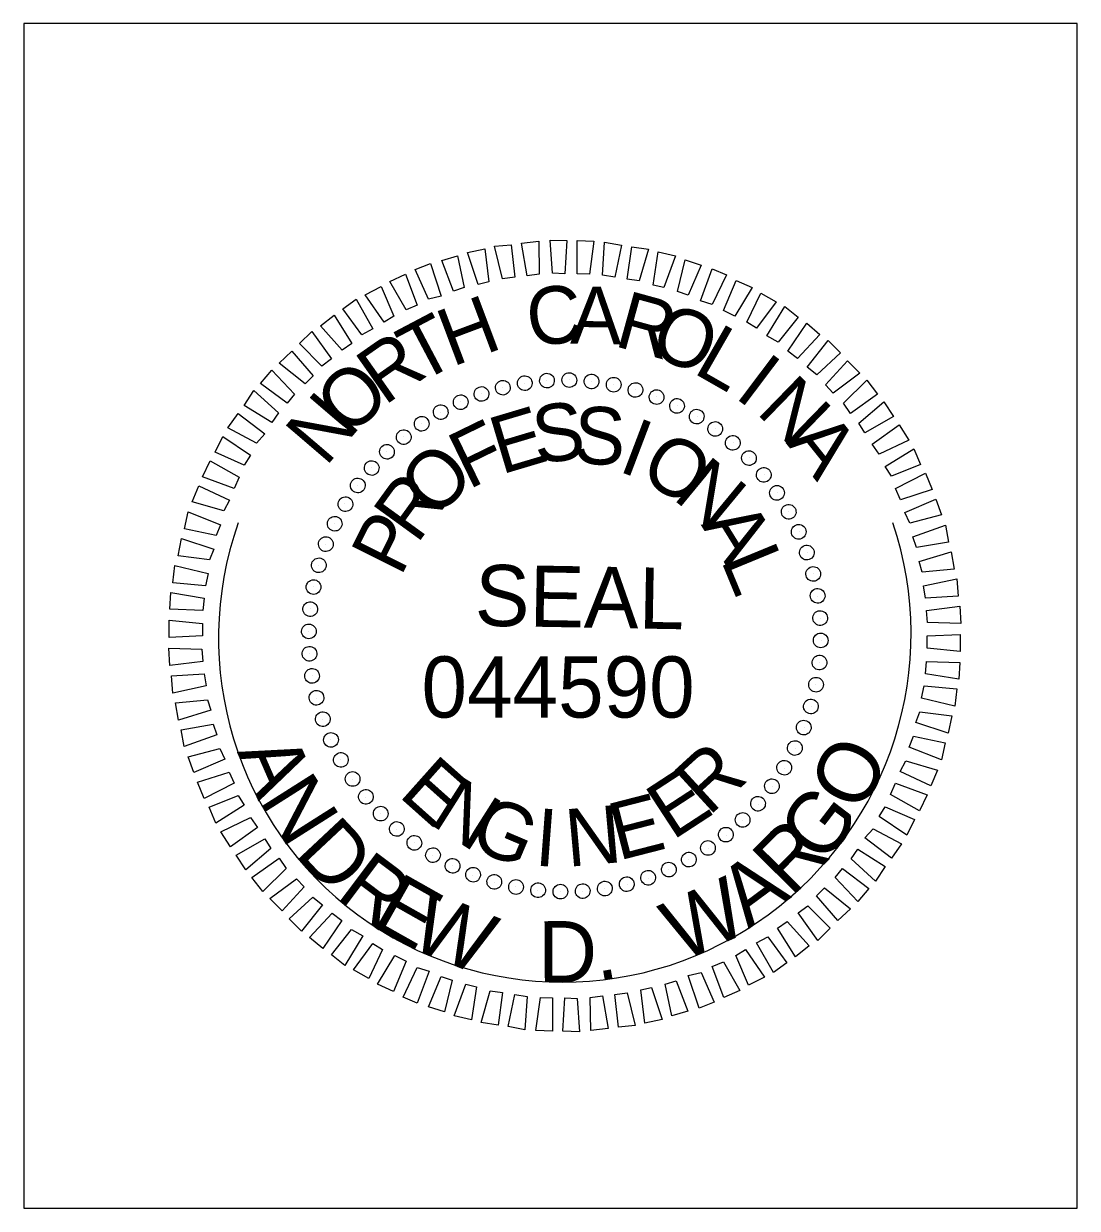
# Model space of a CAD drawing. Extents: x 1882804 to 1884487, y 844572 to 845443.
# Drawn here: x 1884386.6 to 1884486.6, y 845330.9 to 845443.4 of the extents above; entities that cross this region are included whole.
import ezdxf

# ---------------------------------------------------------------- set-up
doc = ezdxf.new("R2010")
doc.units = 0
for name, color, linetype in [('Scratch_Level_1', 7, 'Continuous'), ('Sheet PE Seal Cell', 7, 'Continuous'), ('Sheet Plot Border Inside CELL', 7, 'Continuous')]:
    doc.layers.add(name, color=color, linetype=linetype)

msp = doc.modelspace()

# ---------------------------------------------------------------- linework, layer by layer
at = {"layer": 'Scratch_Level_1'}
msp.add_lwpolyline([(1884386.6, 845330.93), (1884486.6, 845330.93), (1884486.6, 845443.43), (1884386.6, 845443.43)], close=True, dxfattribs=at)
at = {"layer": 'Sheet PE Seal Cell'}
for p, q in [((1884436.27, 845409.56), (1884436.27, 845409.56)), ((1884438.4, 845409.6), (1884438.4, 845409.6)), ((1884440.53, 845409.46), (1884440.53, 845409.46)), ((1884430.02, 845408.3), (1884430.02, 845408.3)), ((1884432.05, 845408.88), (1884432.05, 845408.88)), ((1884434.18, 845409.26), (1884434.18, 845409.26)), ((1884442.61, 845409.12), (1884442.61, 845409.12)), ((1884444.65, 845408.68), (1884444.65, 845408.68)), ((1884428.08, 845407.52), (1884428.08, 845407.52)), ((1884446.68, 845408.01), (1884446.68, 845408.01)), ((1884448.62, 845407.13), (1884448.62, 845407.13)), ((1884426.19, 845406.55), (1884426.19, 845406.55)), ((1884450.51, 845406.16), (1884450.51, 845406.16)), ((1884424.35, 845405.44), (1884424.35, 845405.44)), ((1884452.25, 845404.95), (1884452.25, 845404.95)), ((1884422.66, 845404.23), (1884422.66, 845404.23)), ((1884421.06, 845402.77), (1884421.06, 845402.77)), ((1884453.95, 845403.65), (1884453.95, 845403.65)), ((1884455.45, 845402.19), (1884455.45, 845402.19)), ((1884419.6, 845401.27), (1884419.6, 845401.27)), ((1884456.9, 845400.59), (1884456.9, 845400.59)), ((1884418.3, 845399.58), (1884418.3, 845399.58)), ((1884458.11, 845398.9), (1884458.11, 845398.9)), ((1884417.09, 845397.83), (1884417.09, 845397.83)), ((1884459.23, 845397.06), (1884459.23, 845397.06)), ((1884416.12, 845395.94), (1884416.12, 845395.94)), ((1884460.2, 845395.17), (1884460.2, 845395.17)), ((1884415.25, 845394.01), (1884415.25, 845394.01)), ((1884460.97, 845393.23), (1884460.97, 845393.23)), ((1884414.57, 845391.97), (1884414.57, 845391.97)), ((1884461.55, 845391.2), (1884461.55, 845391.2)), ((1884414.13, 845389.94), (1884414.13, 845389.94)), ((1884461.94, 845389.07), (1884461.94, 845389.07)), ((1884413.79, 845387.86), (1884413.79, 845387.86)), ((1884462.23, 845386.98), (1884462.23, 845386.98)), ((1884413.65, 845385.72), (1884413.65, 845385.72)), ((1884462.28, 845384.85), (1884462.28, 845384.85)), ((1884413.7, 845383.59), (1884413.7, 845383.59)), ((1884462.13, 845382.72), (1884462.13, 845382.72)), ((1884413.99, 845381.51), (1884413.99, 845381.51)), ((1884461.79, 845380.64), (1884461.79, 845380.64)), ((1884414.37, 845379.38), (1884414.37, 845379.38)), ((1884461.36, 845378.6), (1884461.36, 845378.6)), ((1884414.95, 845377.34), (1884414.95, 845377.34)), ((1884460.68, 845376.57), (1884460.68, 845376.57)), ((1884415.73, 845375.41), (1884415.73, 845375.41)), ((1884459.81, 845374.63), (1884459.81, 845374.63)), ((1884416.7, 845373.52), (1884416.7, 845373.52)), ((1884458.84, 845372.74), (1884458.84, 845372.74)), ((1884417.81, 845371.68), (1884417.81, 845371.68)), ((1884457.63, 845371), (1884457.63, 845371)), ((1884419.02, 845369.98), (1884419.02, 845369.98)), ((1884456.32, 845369.3), (1884456.32, 845369.3)), ((1884420.48, 845368.38), (1884420.48, 845368.38)), ((1884454.87, 845367.8), (1884454.87, 845367.8)), ((1884421.98, 845366.93), (1884421.98, 845366.93)), ((1884423.67, 845365.62), (1884423.67, 845365.62)), ((1884453.27, 845366.35), (1884453.27, 845366.35)), ((1884425.42, 845364.41), (1884425.42, 845364.41)), ((1884451.57, 845365.14), (1884451.57, 845365.14)), ((1884427.31, 845363.44), (1884427.31, 845363.44)), ((1884449.73, 845364.02), (1884449.73, 845364.02)), ((1884429.24, 845362.57), (1884429.24, 845362.57)), ((1884445.91, 845362.28), (1884445.91, 845362.28)), ((1884447.84, 845363.06), (1884447.84, 845363.06)), ((1884431.28, 845361.89), (1884431.28, 845361.89)), ((1884433.31, 845361.46), (1884433.31, 845361.46)), ((1884435.4, 845361.12), (1884435.4, 845361.12)), ((1884439.66, 845361.02), (1884439.66, 845361.02)), ((1884441.74, 845361.31), (1884441.74, 845361.31)), ((1884443.87, 845361.7), (1884443.87, 845361.7)), ((1884437.53, 845360.97), (1884437.53, 845360.97))]:
    msp.add_line(p, q, dxfattribs=at)
for points in [[(1884436.8, 845419.73), (1884436.56, 845422.88), (1884438.16, 845422.83), (1884437.96, 845419.68)], [(1884429.73, 845418.66), (1884428.71, 845421.71), (1884430.36, 845422.05), (1884430.75, 845418.9)], [(1884432.05, 845419.19), (1884431.28, 845422.29), (1884432.88, 845422.44), (1884433.22, 845419.34)], [(1884434.38, 845419.49), (1884433.85, 845422.59), (1884435.49, 845422.78), (1884435.54, 845419.63)], [(1884439.12, 845419.68), (1884439.12, 845422.83), (1884440.72, 845422.78), (1884440.29, 845419.63)], [(1884441.55, 845419.53), (1884441.74, 845422.68), (1884443.34, 845422.39), (1884442.71, 845419.34)], [(1884443.87, 845419.15), (1884444.31, 845422.25), (1884445.91, 845422), (1884445.03, 845419)], [(1884446.34, 845418.61), (1884446.83, 845421.76), (1884448.47, 845421.37), (1884447.36, 845418.37)], [(1884425.03, 845417.26), (1884423.77, 845420.07), (1884425.22, 845420.65), (1884426.24, 845417.55)], [(1884427.4, 845418.03), (1884426.29, 845420.94), (1884427.79, 845421.37), (1884428.42, 845418.37)], [(1884448.67, 845417.98), (1884449.39, 845420.99), (1884450.9, 845420.5), (1884449.68, 845417.64)], [(1884422.9, 845416.24), (1884421.35, 845418.95), (1884422.85, 845419.63), (1884423.96, 845416.68)], [(1884450.85, 845417.11), (1884451.96, 845420.16), (1884453.32, 845419.58), (1884451.96, 845416.77)], [(1884420.82, 845415.08), (1884419.02, 845417.69), (1884420.52, 845418.47), (1884421.74, 845415.66)], [(1884453.03, 845416.19), (1884454.24, 845419.05), (1884455.74, 845418.37), (1884454.09, 845415.66)], [(1884418.68, 845413.87), (1884416.89, 845416.34), (1884418.15, 845417.26), (1884419.75, 845414.45)], [(1884455.25, 845415.08), (1884456.56, 845417.84), (1884458.02, 845417.01), (1884456.17, 845414.5)], [(1884457.14, 845413.77), (1884458.84, 845416.58), (1884460.1, 845415.56), (1884458.21, 845413.19)], [(1884416.84, 845412.41), (1884414.76, 845414.74), (1884416.07, 845415.76), (1884417.76, 845413.04)], [(1884414.91, 845410.91), (1884412.77, 845413.04), (1884413.94, 845414.21), (1884415.83, 845411.59)], [(1884459.13, 845412.32), (1884460.92, 845414.98), (1884462.18, 845413.91), (1884460.05, 845411.64)], [(1884460.97, 845410.81), (1884462.96, 845413.33), (1884464.12, 845412.17), (1884461.89, 845410.09)], [(1884413.31, 845409.22), (1884410.84, 845411.2), (1884412.05, 845412.32), (1884414.08, 845409.99)], [(1884411.61, 845407.38), (1884409.09, 845409.26), (1884410.16, 845410.52), (1884412.29, 845408.25)], [(1884462.71, 845409.12), (1884464.8, 845411.4), (1884465.96, 845410.23), (1884463.44, 845408.34)], [(1884464.41, 845407.38), (1884466.64, 845409.56), (1884467.65, 845408.25), (1884465.09, 845406.41)], [(1884410.16, 845405.54), (1884407.54, 845407.18), (1884408.46, 845408.59), (1884410.79, 845406.46)], [(1884465.86, 845405.49), (1884468.24, 845407.52), (1884469.16, 845406.12), (1884466.44, 845404.57)], [(1884408.71, 845403.6), (1884405.99, 845405.05), (1884406.96, 845406.41), (1884409.48, 845404.47)], [(1884467.12, 845403.5), (1884469.69, 845405.34), (1884470.61, 845403.89), (1884467.8, 845402.53)], [(1884407.54, 845401.51), (1884404.78, 845402.73), (1884405.51, 845404.23), (1884408.12, 845402.44)], [(1884468.38, 845401.37), (1884471.09, 845403.06), (1884471.72, 845401.56), (1884468.96, 845400.45)], [(1884406.57, 845399.29), (1884403.57, 845400.4), (1884404.3, 845401.9), (1884407.06, 845400.35)], [(1884469.35, 845399.29), (1884472.21, 845400.74), (1884472.84, 845399.19), (1884469.83, 845398.22)], [(1884405.61, 845397.16), (1884402.6, 845398.03), (1884403.23, 845399.53), (1884406.14, 845398.17)], [(1884470.22, 845397.01), (1884473.18, 845398.27), (1884473.71, 845396.77), (1884470.71, 845395.99)], [(1884404.88, 845394.83), (1884401.88, 845395.46), (1884402.22, 845397.06), (1884405.27, 845395.85)], [(1884471, 845394.69), (1884474.1, 845395.8), (1884474.39, 845394.2), (1884471.34, 845393.67)], [(1884404.25, 845392.51), (1884401.25, 845392.89), (1884401.59, 845394.54), (1884404.64, 845393.52)], [(1884471.58, 845392.36), (1884474.63, 845393.28), (1884474.92, 845391.63), (1884471.87, 845391.34)], [(1884403.86, 845390.04), (1884400.76, 845390.33), (1884400.96, 845391.97), (1884404.1, 845391.2)], [(1884472.01, 845390.04), (1884475.16, 845390.71), (1884475.31, 845389.07), (1884472.21, 845388.87)], [(1884403.62, 845387.71), (1884400.47, 845387.81), (1884400.57, 845389.41), (1884403.72, 845388.87)], [(1884472.3, 845387.71), (1884475.45, 845388.1), (1884475.55, 845386.45), (1884472.4, 845386.55)], [(1884403.57, 845385.29), (1884400.42, 845385.14), (1884400.42, 845386.79), (1884403.57, 845386.45)], [(1884472.35, 845385.29), (1884475.5, 845385.43), (1884475.5, 845383.79), (1884472.35, 845384.13)], [(1884403.62, 845382.87), (1884400.47, 845382.48), (1884400.37, 845384.13), (1884403.52, 845384.03)], [(1884472.3, 845382.87), (1884475.45, 845382.77), (1884475.36, 845381.17), (1884472.21, 845381.7)], [(1884403.91, 845380.54), (1884400.76, 845379.86), (1884400.62, 845381.51), (1884403.72, 845381.7)], [(1884472.06, 845380.54), (1884475.16, 845380.25), (1884474.97, 845378.6), (1884471.82, 845379.38)], [(1884404.35, 845378.22), (1884401.3, 845377.3), (1884401, 845378.94), (1884404.06, 845379.23)], [(1884471.67, 845378.07), (1884474.68, 845377.68), (1884474.34, 845376.04), (1884471.29, 845377.05)], [(1884404.93, 845375.89), (1884401.83, 845374.78), (1884401.54, 845376.38), (1884404.59, 845376.91)], [(1884471.05, 845375.75), (1884474.05, 845375.12), (1884473.71, 845373.52), (1884470.66, 845374.73)], [(1884405.7, 845373.57), (1884402.75, 845372.31), (1884402.22, 845373.81), (1884405.22, 845374.58)], [(1884470.32, 845373.42), (1884473.32, 845372.55), (1884472.69, 845371.05), (1884469.79, 845372.4)], [(1884406.57, 845371.29), (1884403.72, 845369.84), (1884403.09, 845371.39), (1884406.09, 845372.36)], [(1884469.35, 845371.29), (1884472.35, 845370.18), (1884471.63, 845368.67), (1884468.87, 845370.22)], [(1884407.54, 845369.21), (1884404.83, 845367.51), (1884404.2, 845369.01), (1884406.96, 845370.13)], [(1884468.38, 845369.06), (1884471.14, 845367.85), (1884470.42, 845366.35), (1884467.8, 845368.14)], [(1884408.8, 845367.08), (1884406.24, 845365.24), (1884405.32, 845366.69), (1884408.12, 845368.04)], [(1884467.22, 845366.98), (1884469.93, 845365.53), (1884468.96, 845364.17), (1884466.44, 845366.11)], [(1884410.06, 845365.09), (1884407.69, 845363.06), (1884406.77, 845364.46), (1884409.48, 845366.01)], [(1884465.77, 845365.04), (1884468.38, 845363.39), (1884467.46, 845361.99), (1884465.14, 845364.12)], [(1884411.52, 845363.2), (1884409.29, 845361.02), (1884408.27, 845362.33), (1884410.84, 845364.17)], [(1884413.21, 845361.46), (1884411.13, 845359.18), (1884409.97, 845360.34), (1884412.48, 845362.23)], [(1884464.31, 845363.2), (1884466.83, 845361.31), (1884465.77, 845360.05), (1884463.63, 845362.33)], [(1884462.62, 845361.36), (1884465.09, 845359.37), (1884463.88, 845358.26), (1884461.84, 845360.59)], [(1884414.95, 845359.76), (1884412.97, 845357.24), (1884411.81, 845358.41), (1884414.03, 845360.49)], [(1884416.8, 845358.26), (1884415, 845355.6), (1884413.74, 845356.66), (1884415.87, 845358.94)], [(1884461.02, 845359.66), (1884463.15, 845357.53), (1884461.99, 845356.37), (1884460.1, 845358.99)], [(1884459.08, 845358.16), (1884461.16, 845355.84), (1884459.86, 845354.82), (1884458.16, 845357.53)], [(1884418.78, 845356.81), (1884417.09, 845354), (1884415.83, 845355.01), (1884417.72, 845357.39)], [(1884457.24, 845356.71), (1884459.03, 845354.24), (1884457.77, 845353.32), (1884456.17, 845356.13)], [(1884420.67, 845355.5), (1884419.36, 845352.74), (1884417.91, 845353.56), (1884419.75, 845356.08)], [(1884455.11, 845355.5), (1884456.9, 845352.88), (1884455.4, 845352.11), (1884454.19, 845354.92)], [(1884422.9, 845354.39), (1884421.69, 845351.53), (1884420.19, 845352.21), (1884421.83, 845354.92)], [(1884453.03, 845354.34), (1884454.58, 845351.62), (1884453.07, 845350.95), (1884451.96, 845353.9)], [(1884425.08, 845353.46), (1884423.96, 845350.41), (1884422.61, 845350.99), (1884423.96, 845353.8)], [(1884450.9, 845353.32), (1884452.15, 845350.51), (1884450.7, 845349.93), (1884449.68, 845353.03)], [(1884427.26, 845352.59), (1884426.53, 845349.59), (1884425.03, 845350.07), (1884426.24, 845352.93)], [(1884429.58, 845351.96), (1884429.1, 845348.81), (1884427.45, 845349.2), (1884428.57, 845352.21)], [(1884448.52, 845352.54), (1884449.64, 845349.64), (1884448.13, 845349.2), (1884447.5, 845352.21)], [(1884432.05, 845351.43), (1884431.62, 845348.33), (1884430.02, 845348.57), (1884430.89, 845351.58)], [(1884434.38, 845351.04), (1884434.18, 845347.89), (1884432.59, 845348.19), (1884433.22, 845351.24)], [(1884436.8, 845350.9), (1884436.8, 845347.75), (1884435.2, 845347.8), (1884435.64, 845350.95)], [(1884439.12, 845350.85), (1884439.37, 845347.7), (1884437.77, 845347.75), (1884437.96, 845350.9)], [(1884441.55, 845351.09), (1884442.08, 845347.99), (1884440.43, 845347.8), (1884440.38, 845350.95)], [(1884443.87, 845351.38), (1884444.65, 845348.28), (1884443.05, 845348.14), (1884442.71, 845351.24)], [(1884446.2, 845351.91), (1884447.21, 845348.86), (1884445.57, 845348.52), (1884445.18, 845351.67)]]:
    msp.add_lwpolyline(points, close=True, dxfattribs=at)
for centre, major_axis in [((1884432.08, 845408.86), (-0.169, 0.677)), ((1884434.16, 845409.29), (-0.109, 0.689)), ((1884436.27, 845409.53), (-0.049, 0.696)), ((1884438.39, 845409.58), (0.012, 0.697)), ((1884440.5, 845409.45), (0.073, 0.694)), ((1884442.6, 845409.14), (0.133, 0.685)), ((1884444.66, 845408.64), (0.192, 0.67)), ((1884428.08, 845407.48), (-0.284, 0.637)), ((1884430.05, 845408.26), (-0.227, 0.66)), ((1884446.67, 845407.97), (0.25, 0.651)), ((1884426.18, 845406.54), (-0.338, 0.61)), ((1884448.61, 845407.13), (0.306, 0.627)), ((1884424.38, 845405.43), (-0.39, 0.578)), ((1884450.48, 845406.11), (0.359, 0.598)), ((1884422.67, 845404.17), (-0.439, 0.542)), ((1884452.24, 845404.94), (0.41, 0.564)), ((1884453.9, 845403.62), (0.458, 0.526)), ((1884421.08, 845402.77), (-0.485, 0.502)), ((1884455.44, 845402.17), (0.502, 0.485)), ((1884419.63, 845401.23), (-0.526, 0.458)), ((1884456.84, 845400.58), (0.542, 0.439)), ((1884418.31, 845399.57), (-0.564, 0.41)), ((1884458.1, 845398.87), (0.578, 0.39)), ((1884417.14, 845397.8), (-0.598, 0.359)), ((1884459.21, 845397.07), (0.61, 0.338)), ((1884416.12, 845395.94), (-0.627, 0.306)), ((1884460.16, 845395.17), (0.637, 0.284)), ((1884415.28, 845394), (-0.651, 0.25)), ((1884460.93, 845393.2), (0.66, 0.227)), ((1884414.61, 845391.99), (-0.67, 0.192)), ((1884461.54, 845391.17), (0.677, 0.169)), ((1884414.11, 845389.92), (-0.685, 0.133)), ((1884461.96, 845389.09), (0.689, 0.109)), ((1884413.8, 845387.83), (-0.694, 0.073)), ((1884462.2, 845386.98), (0.696, 0.049)), ((1884413.67, 845385.71), (-0.697, 0.012)), ((1884462.25, 845384.86), (0.697, -0.012)), ((1884413.73, 845383.59), (-0.696, -0.049)), ((1884462.13, 845382.75), (0.694, -0.073)), ((1884413.97, 845381.49), (-0.689, -0.109)), ((1884461.81, 845380.65), (0.685, -0.133)), ((1884414.39, 845379.41), (-0.677, -0.169)), ((1884461.32, 845378.59), (0.67, -0.192)), ((1884414.99, 845377.38), (-0.66, -0.227)), ((1884460.64, 845376.58), (0.651, -0.25)), ((1884415.77, 845375.41), (-0.637, -0.284)), ((1884459.8, 845374.64), (0.627, -0.306)), ((1884416.71, 845373.51), (-0.61, -0.338)), ((1884458.79, 845372.77), (0.598, -0.359)), ((1884417.82, 845371.7), (-0.578, -0.39)), ((1884457.62, 845371.01), (0.564, -0.41)), ((1884419.08, 845370), (-0.542, -0.439)), ((1884456.3, 845369.35), (0.526, -0.458)), ((1884420.49, 845368.41), (-0.502, -0.485)), ((1884454.84, 845367.81), (0.485, -0.502)), ((1884422.02, 845366.95), (-0.458, -0.526)), ((1884453.25, 845366.41), (0.439, -0.542)), ((1884423.68, 845365.63), (-0.41, -0.564)), ((1884451.55, 845365.15), (0.39, -0.578)), ((1884425.45, 845364.46), (-0.359, -0.598)), ((1884449.74, 845364.04), (0.338, -0.61)), ((1884427.31, 845363.45), (-0.306, -0.627)), ((1884429.26, 845362.61), (-0.25, -0.651)), ((1884447.84, 845363.09), (0.284, -0.637)), ((1884431.27, 845361.93), (-0.192, -0.67)), ((1884433.33, 845361.44), (-0.133, -0.685)), ((1884443.84, 845361.71), (0.169, -0.677)), ((1884445.87, 845362.32), (0.227, -0.66)), ((1884435.42, 845361.13), (-0.073, -0.694)), ((1884437.54, 845361), (-0.012, -0.697)), ((1884439.66, 845361.05), (0.049, -0.696)), ((1884441.76, 845361.29), (0.109, -0.689))]:
    msp.add_ellipse(centre, major_axis=major_axis, ratio=0.999708, dxfattribs=at)
at = {"layer": 'Sheet Plot Border Inside CELL'}
msp.add_ellipse((1884437.96, 845385.29), major_axis=(21.84, 24.72), ratio=0.993455, start_param=1.958957, end_param=5.764947, dxfattribs=at)

# ---------------------------------------------------------------- texts
at = {"layer": 'Sheet PE Seal Cell'}
for s, height, rotation, p in [('C', 5.46, 6.2199, (1884434.62, 845412.75)), ('A', 5.46, 359.0203, (1884438.45, 845413.04)), ('H', 5.46, 20.6195, (1884427.26, 845410.81)), ('R', 5.46, 344.6211, (1884442.52, 845412.85)), ('O', 5.46, 337.4212, (1884445.76, 845412.12)), ('T', 5.46, 27.8198, (1884424.11, 845409.22)), ('L', 5.46, 330.2209, (1884450.02, 845410.33)), ('R', 5.46, 35.0205, (1884420.82, 845407.09)), ('I', 5.46, 323.0201, (1884453.95, 845408.01)), ('O', 5.46, 42.2217, (1884417.47, 845404.08)), ('N', 5.46, 315.8189, (1884456.03, 845406.5)), ('N', 5.46, 49.4235, (1884415.25, 845401.27)), ('S', 5.46, 7.2556, (1884435.25, 845401.61)), ('S', 5.46, 357.9004, (1884438.74, 845401.66)), ('E', 5.46, 16.6111, (1884431.91, 845400.59)), ('F', 5.46, 25.967, (1884428.81, 845399.14)), ('I', 5.46, 339.1896, (1884442.9, 845400.98)), ('A', 5.46, 308.6172, (1884458.89, 845403.65)), ('O', 5.46, 329.8335, (1884444.84, 845400.3)), ('O', 5.46, 44.6812, (1884425.61, 845396.28)), ('N', 5.46, 320.4766, (1884448.09, 845398.37)), ('R', 5.46, 54.0397, (1884423.92, 845393.91)), ('P', 5.46, 63.3989, (1884422.37, 845390.81)), ('A', 5.46, 301.7603, (1884450.85, 845395.85)), ('L', 5.46, 292.4008, (1884452.74, 845392.51)), ('SEAL', 5.811, 359, (1884429.39, 845386.26)), ('A', 5.81, 293.5515, (1884406.82, 845374.28)), ('R', 5.46, 42.4814, (1884451.62, 845368.09)), ('O', 5.81, 63.1672, (1884466.13, 845368.34)), ('E', 5.46, 318.2769, (1884422.07, 845370.13)), ('E', 5.46, 33.1241, (1884448.18, 845365.82)), ('N', 5.81, 302.3949, (1884408.84, 845369.65)), ('N', 5.46, 327.634, (1884424.98, 845367.51)), ('E', 5.46, 14.4118, (1884443.05, 845363.93)), ('G', 5.81, 52.6151, (1884462.49, 845363.41)), ('G', 5.46, 336.9902, (1884428.66, 845365.33)), ('I', 5.46, 355.7012, (1884435.01, 845363.49)), ('N', 5.46, 5.0564, (1884438.25, 845363.35)), ('D', 5.81, 313.1429, (1884412.2, 845364.54)), ('R', 5.81, 45.26, (1884459.45, 845360.41)), ('R', 5.81, 323.0459, (1884416.09, 845360.46)), ('A', 5.81, 36.5645, (1884455.4, 845357.41)), ('E', 5.81, 330.5439, (1884419.48, 845357.86)), ('W', 5.81, 24.216, (1884448.97, 845354.27)), ('W', 5.81, 337.6629, (1884422.98, 845355.81)), ('D', 5.81, 0.3436, (1884435.43, 845352.38)), ('.', 5.81, 10.1446, (1884441.06, 845352.47))]:
    msp.add_text(s, height=height, rotation=rotation, dxfattribs=at).set_placement(p)
msp.add_text('044590 ', height=5.811, dxfattribs=at).set_placement((1884424.36, 845377.53))

doc.saveas('drawing.dxf')
